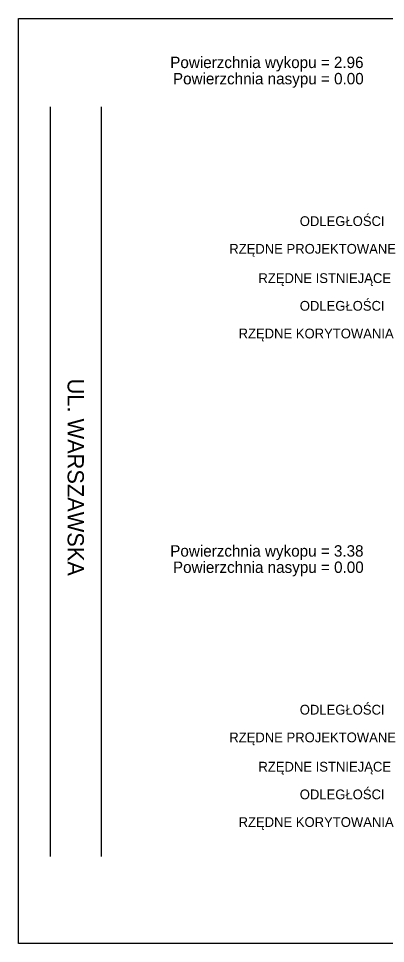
# Model space of a CAD drawing. Extents: x 7492871 to 7493499, y 5802964 to 5802992.
# Drawn here: x 7492871.37 to 7492882.66, y 5802963.88 to 5802992.28 of the extents above; entities that cross this region are included whole.
import ezdxf

# ---------------------------------------------------------------- set-up
doc = ezdxf.new("R2010")
doc.units = 0
for name, color, linetype in [('_wydruk', 7, 'Continuous'), ('d_pop_nasyp_opis', 7, 'Continuous'), ('d_pop_wykop_opis', 7, 'Continuous'), ('opisy_ramki_pop', 7, 'Continuous'), ('pop_opis', 7, 'Continuous'), ('pop_pikietaz', 7, 'Continuous')]:
    doc.layers.add(name, color=color, linetype=linetype)

msp = doc.modelspace()

# ---------------------------------------------------------------- linework, layer by layer
at = {"layer": '_wydruk'}
msp.add_lwpolyline([(7492871.369, 5802992.281), (7493499.283, 5802992.281), (7493499.283, 5802963.881), (7492871.369, 5802963.881)], close=True, dxfattribs=at)
at = {"layer": 'opisy_ramki_pop'}
for p, q in [((7492872.347, 5802989.573), (7492872.347, 5802966.547)), ((7492873.913, 5802989.573), (7492873.913, 5802966.547))]:
    msp.add_line(p, q, dxfattribs=at)

# ---------------------------------------------------------------- texts
at = {"layer": 'd_pop_nasyp_opis'}
for p in [(7492876.12, 5802990.259), (7492876.12, 5802975.259)]:
    msp.add_text('Powierzchnia nasypu = 0.00', height=0.35, dxfattribs=at).set_placement(p)
at = {"layer": 'd_pop_wykop_opis'}
for s, p in [('Powierzchnia wykopu = 2.96', (7492876.037, 5802990.759)), ('Powierzchnia wykopu = 3.38', (7492876.037, 5802975.759))]:
    msp.add_text(s, height=0.35, dxfattribs=at).set_placement(p)
at = {"layer": 'pop_opis'}
for s, p in [('ODLEGŁOŚCI', (7492880.021, 5802985.909)), ('ODLEGŁOŚCI', (7492880.021, 5802985.909)), ('ODLEGŁOŚCI', (7492880.021, 5802985.909)), ('ODLEGŁOŚCI', (7492880.021, 5802985.909)), ('RZĘDNE PROJEKTOWANE', (7492877.853, 5802985.059)), ('RZĘDNE PROJEKTOWANE', (7492877.853, 5802985.059)), ('RZĘDNE PROJEKTOWANE', (7492877.853, 5802985.059)), ('RZĘDNE PROJEKTOWANE', (7492877.853, 5802985.059)), ('RZĘDNE ISTNIEJĄCE', (7492878.749, 5802984.159)), ('ODLEGŁOŚCI', (7492880.021, 5802983.309)), ('RZĘDNE KORYTOWANIA', (7492878.139, 5802982.459)), ('ODLEGŁOŚCI', (7492880.021, 5802970.909)), ('ODLEGŁOŚCI', (7492880.021, 5802970.909)), ('ODLEGŁOŚCI', (7492880.021, 5802970.909)), ('ODLEGŁOŚCI', (7492880.021, 5802970.909)), ('RZĘDNE PROJEKTOWANE', (7492877.853, 5802970.059)), ('RZĘDNE PROJEKTOWANE', (7492877.853, 5802970.059)), ('RZĘDNE PROJEKTOWANE', (7492877.853, 5802970.059)), ('RZĘDNE PROJEKTOWANE', (7492877.853, 5802970.059)), ('RZĘDNE ISTNIEJĄCE', (7492878.749, 5802969.159)), ('ODLEGŁOŚCI', (7492880.021, 5802968.309)), ('RZĘDNE KORYTOWANIA', (7492878.139, 5802967.459))]:
    msp.add_text(s, height=0.3, dxfattribs=at).set_placement(p)
at = {"layer": 'pop_pikietaz'}
msp.add_text('UL. WARSZAWSKA', height=0.5, rotation=270, dxfattribs=at).set_placement((7492872.88, 5802981.224))

doc.saveas('drawing.dxf')
